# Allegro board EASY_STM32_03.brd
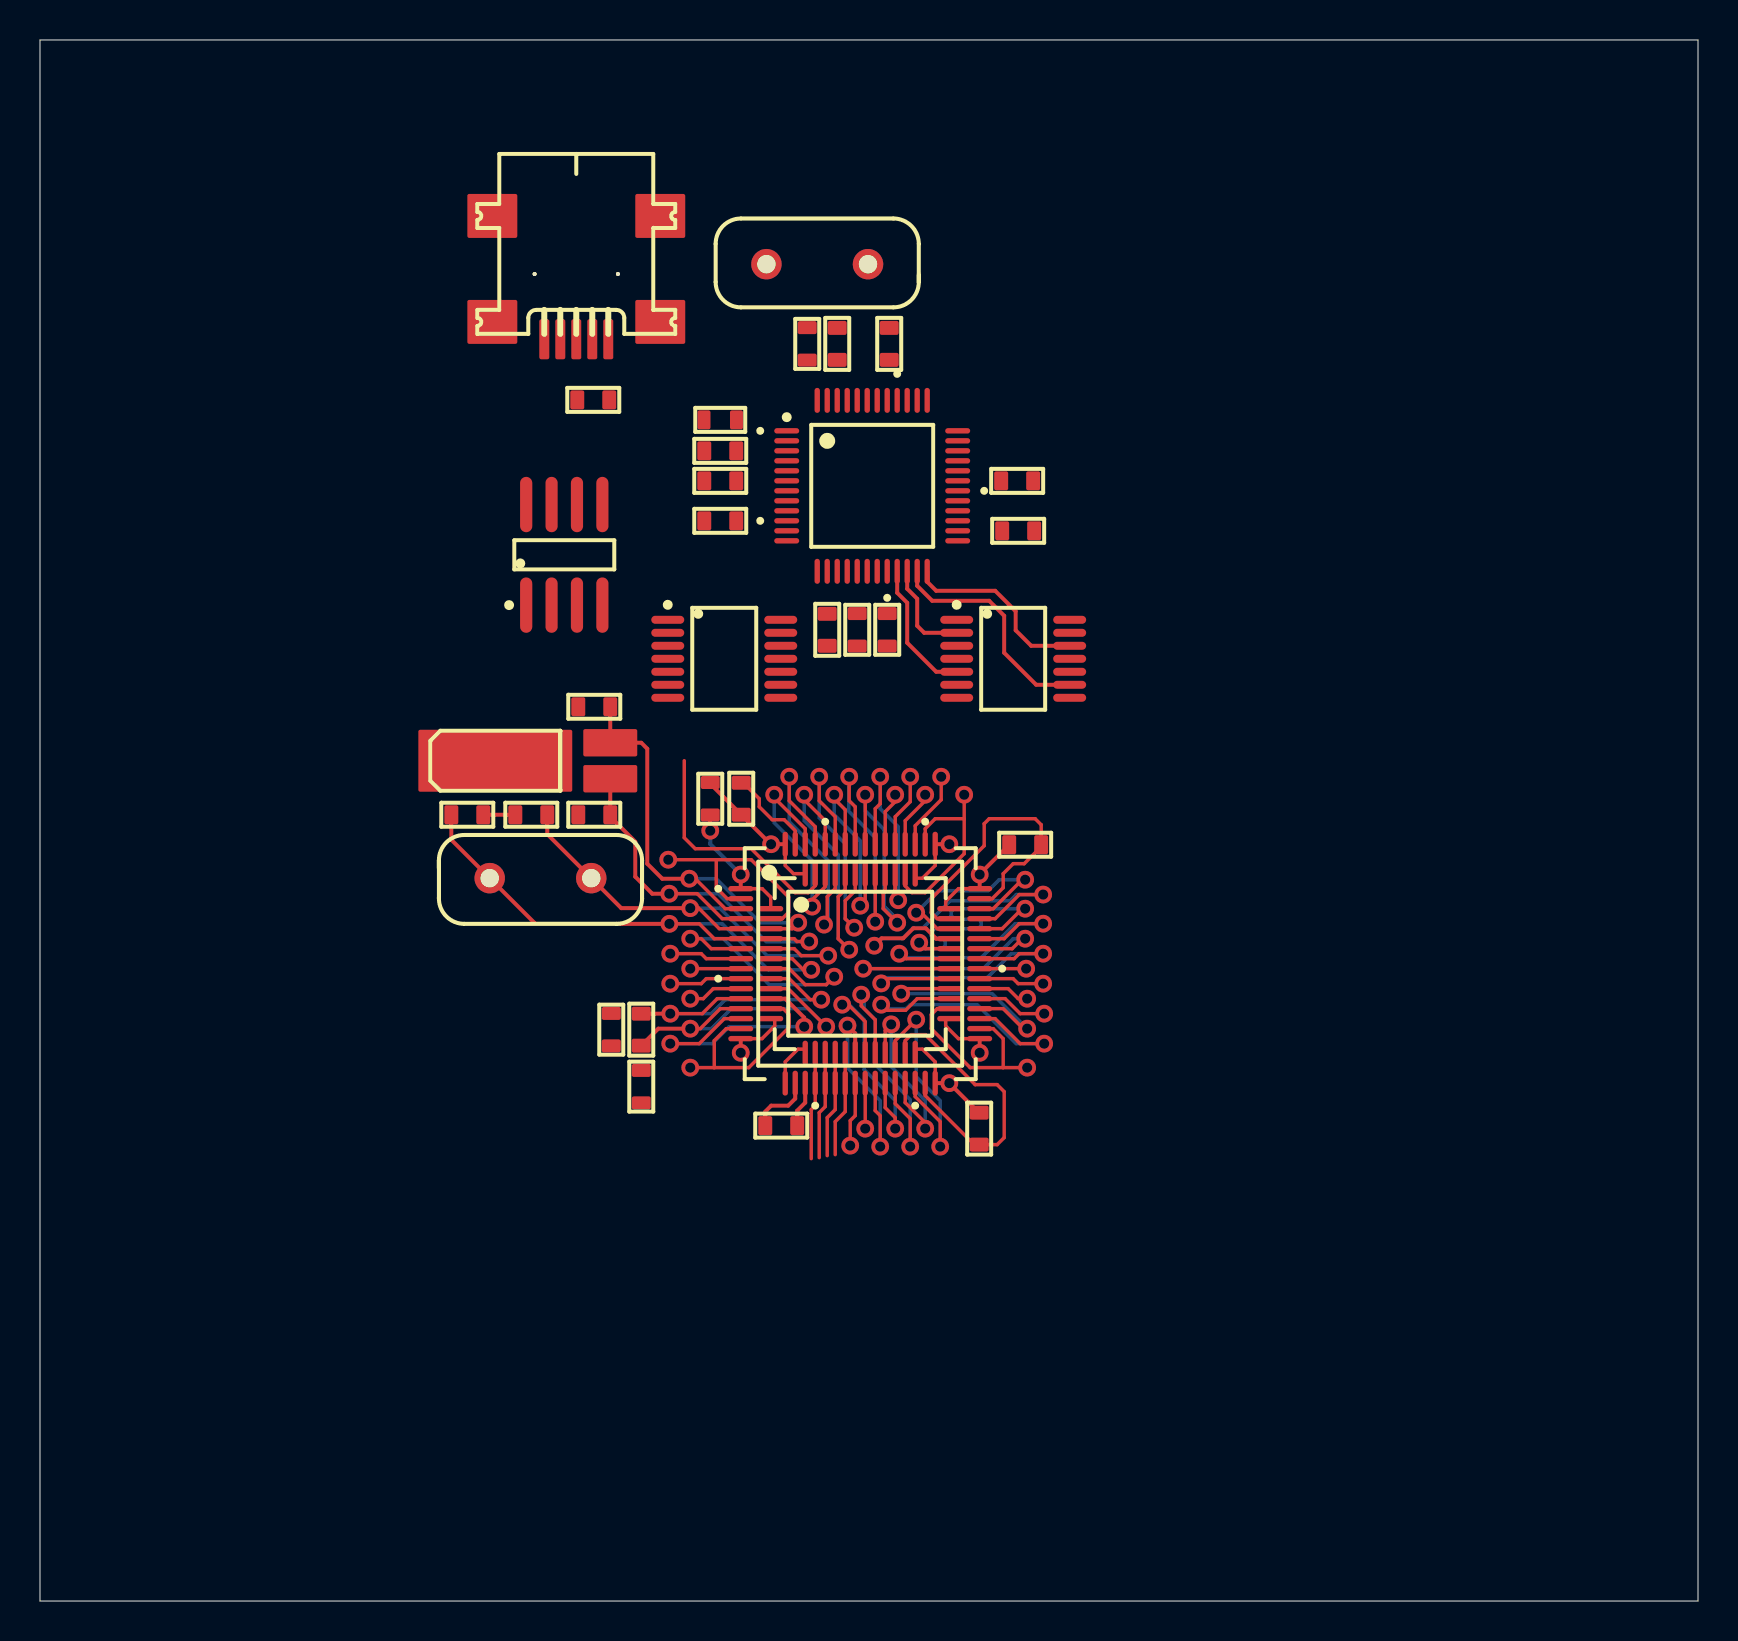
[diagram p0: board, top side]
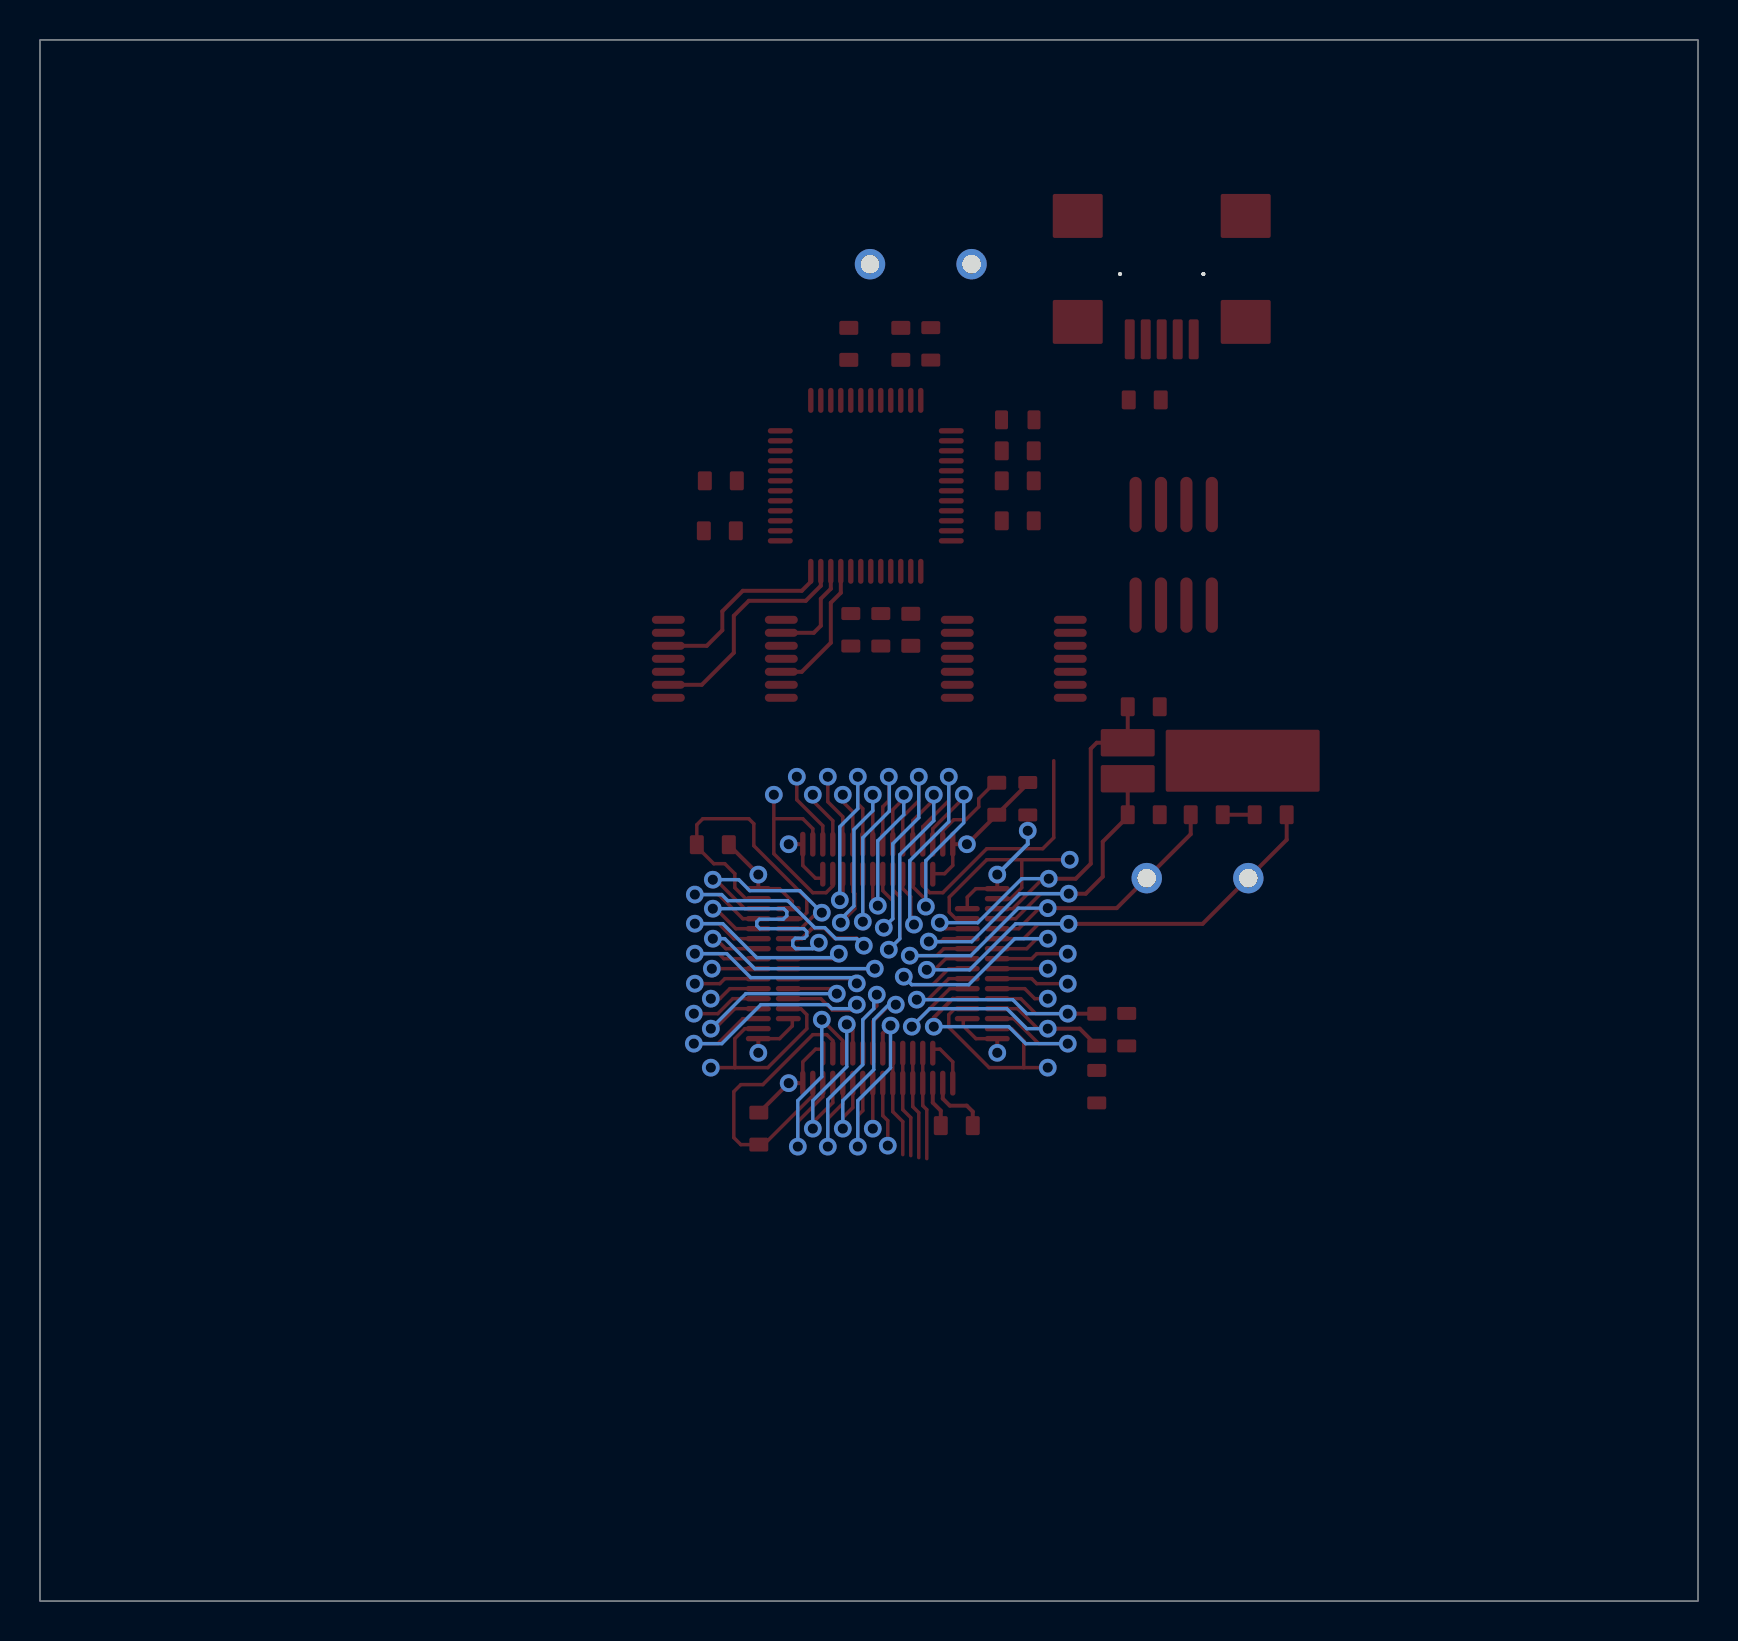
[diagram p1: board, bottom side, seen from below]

Outline 82.92 x 78.08 mm; copper layers: TOP, BOTTOM. Coordinates in mm from the lower left corner of the outline.
Outline path: 0,78.08 0,0 82.92,0 82.92,78.08 0,78.08

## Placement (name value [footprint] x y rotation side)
C1  22pF  [CAP0603_B]  24.57 39.33 180 top
C2  22p  [CAP0603_B]  21.37 39.33 0 top
C3  15p  [CAP0603_B]  27.72 39.33 180 top
C4  15p  [CAP0603_B]  27.72 44.73 180 top
C5  100n  [CAP0603_B]  30.07 28.58 90 top
C6  100n  [CAP0603_B]  46.97 23.63 270 top
C7  100n  [CAP0603_B]  49.27 37.83 0 top
C8  100n  [CAP0603_B]  35.07 40.13 90 top
C9  100n  [CAP0603_B]  37.07 23.78 180 top
C10  10u  [CAP0603_B]  27.67 60.08 0 top
C11  100n  [CAP0603_B]  34.02 57.53 180 top
C12  100n  [CAP0603_B]  42.47 62.88 90 top
C14  100n  [CAP0603_B]  34.02 54.03 180 top
C15  100n  [CAP0603_B]  39.37 48.58 270 top
C16  100n  [CAP0603_B]  48.92 53.53 0 top
C17  100n  [CAP0603_B]  48.87 56.03 0 top
C18  100n  [CAP0603_B]  39.87 62.88 90 top
C19  100n  [CAP0603_B]  34.02 56.03 180 top
J1  USB_MB  [HIROSE-US60-MB-5ST]  26.82 72.38 180 top
R1  0R  [RES0603_B]  33.52 40.13 90 top
R2  0R  [RES0603_B]  30.07 25.73 270 top
R3  0R  [RES0603_B]  28.57 28.58 270 top
R4  470R  [RES0603_B]  38.37 62.88 270 top
R7  10K  [RES0603_B]  42.37 48.58 270 top
R13  1K5  [RES0603_B]  34.02 59.08 0 top
R14  100K  [RES0603_B]  40.87 48.58 270 top
U1  STM32F103RCT6  [LQFP64_MODIFIED]  41.02 31.88 0 top
U2  STM32F100  [LQFP48L_MODIFIED]  41.02 31.88 0 top
U3  FT2232D  [LQFP48L]  41.62 55.78 0 top
U4  AT93C46-10SI-2.7  [SOIC8S1JEDECM]  26.22 52.33 0 top
U5  74LVC125A  [TSOP65P640X120-14]  48.67 47.13 270 top
U6  74LVC125A  [TSOP65P640X120-14]  34.22 47.13 270 top
Y1  8M  [XTAL_DIP]  22.49 36.16 0 top
Y2  32.768KHz  [RTC-CRYSTAL]  24.52 42.03 90 top
Y3  6M  [XTAL_DIP]  41.41 66.86 180 top

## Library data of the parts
C1-C9 = C1005_0: User Part Number: pn; Tolerance: RichardLC
C10-C12 C14-C19 = CAP NP_0: User Part Number: pn; Tolerance: RichardLC
J1 = CON9: User Part Number: pn; Tolerance: RichardLC
R1-R4 R7 R13 R14 = R_0: User Part Number: pn; Tolerance: RichardLC
U1 = STM32F103RCT6_2: User Part Number: pn; Tolerance: RichardLC
U2 = STM32F100_1: User Part Number: pn; Tolerance: RichardLC
U3 = FT2232D_0: User Part Number: pn; Tolerance: RichardLC
U4 = 93C46_2: User Part Number: pn; Tolerance: RichardLC
U5 U6 = 74HC125/LCC_0: User Part Number: pn; Tolerance: RichardLC
Y1 Y3 = ZTB: Tolerance: ***; User Part Number: ***
Y2 = ZTA_0: User Part Number: pn; Tolerance: RichardLC

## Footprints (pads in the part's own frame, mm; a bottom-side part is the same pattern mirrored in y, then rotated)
CAP0603_B
  custom 0.175x0.175 smd: 1(-0.8,0) 2(0.8,0)
HIROSE-US60-MB-5ST
  round 0.2 hole 0.9 unplated: (-2.083,6.005) (2.083,6.005)
  custom 0.125x0.125 smd: 1(-1.6,9.271) 2(-0.8,9.271) 3(0,9.271) 4(0.8,9.271) 5(1.6,9.271)
  custom 0.55x0.55 smd: 6(-4.2,3.1) 7(4.2,3.1) 8(-4.2,8.4) 9(4.2,8.4)
LQFP48L
  oval 1.25x0.27 smd: 1(-4.275,2.75) 2(-4.275,2.25) 3(-4.275,1.75) 4(-4.275,1.25) 5(-4.275,0.75) 6(-4.275,0.25) 7(-4.275,-0.25) 8(-4.275,-0.75) 9(-4.275,-1.25) 10(-4.275,-1.75) 11(-4.275,-2.25) 12(-4.275,-2.75) 25(4.275,-2.75) 26(4.275,-2.25) 27(4.275,-1.75) 28(4.275,-1.25) 29(4.275,-0.75) 30(4.275,-0.25) 31(4.275,0.25) 32(4.275,0.75) 33(4.275,1.25) 34(4.275,1.75) 35(4.275,2.25) 36(4.275,2.75)
  oval 0.27x1.25 smd: 13(-2.75,-4.275) 14(-2.25,-4.275) 15(-1.75,-4.275) 16(-1.25,-4.275) 17(-0.75,-4.275) 18(-0.25,-4.275) 19(0.25,-4.275) 20(0.75,-4.275) 21(1.25,-4.275) 22(1.75,-4.275) 23(2.25,-4.275) 24(2.75,-4.275) 37(2.75,4.275) 38(2.25,4.275) 39(1.75,4.275) 40(1.25,4.275) 41(0.75,4.275) 42(0.25,4.275) 43(-0.25,4.275) 44(-0.75,4.275) 45(-1.25,4.275) 46(-1.75,4.275) 47(-2.25,4.275) 48(-2.75,4.275)
LQFP48L_MODIFIED
  oval 1.25x0.27 smd: 1(-4.475,2.75) 2(-4.475,2.25) 3(-4.475,1.75) 4(-4.475,1.25) 5(-4.475,0.75) 6(-4.475,0.25) 7(-4.475,-0.25) 8(-4.475,-0.75) 9(-4.475,-1.25) 10(-4.475,-1.75) 11(-4.475,-2.25) 12(-4.475,-2.75) 25(4.475,-2.75) 26(4.475,-2.25) 27(4.475,-1.75) 28(4.475,-1.25) 29(4.475,-0.75) 30(4.475,-0.25) 31(4.475,0.25) 32(4.475,0.75) 33(4.475,1.25) 34(4.475,1.75) 35(4.475,2.25) 36(4.475,2.75)
  oval 0.27x1.25 smd: 13(-2.75,-4.475) 14(-2.25,-4.475) 15(-1.75,-4.475) 16(-1.25,-4.475) 17(-0.75,-4.475) 18(-0.25,-4.475) 19(0.25,-4.475) 20(0.75,-4.475) 21(1.25,-4.475) 22(1.75,-4.475) 23(2.25,-4.475) 24(2.75,-4.475) 37(2.75,4.475) 38(2.25,4.475) 39(1.75,4.475) 40(1.25,4.475) 41(0.75,4.475) 42(0.25,4.475) 43(-0.25,4.475) 44(-0.75,4.475) 45(-1.25,4.475) 46(-1.75,4.475) 47(-2.25,4.475) 48(-2.75,4.475)
LQFP64_MODIFIED
  oval 1.25x0.27 smd: 1(-5.975,3.75) 2(-5.975,3.25) 3(-5.975,2.75) 4(-5.975,2.25) 5(-5.975,1.75) 6(-5.975,1.25) 7(-5.975,0.75) 8(-5.975,0.25) 9(-5.975,-0.25) 10(-5.975,-0.75) 11(-5.975,-1.25) 12(-5.975,-1.75) 13(-5.975,-2.25) 14(-5.975,-2.75) 15(-5.975,-3.25) 16(-5.975,-3.75) 33(5.975,-3.75) 34(5.975,-3.25) 35(5.975,-2.75) 36(5.975,-2.25) 37(5.975,-1.75) 38(5.975,-1.25) 39(5.975,-0.75) 40(5.975,-0.25) 41(5.975,0.25) 42(5.975,0.75) 43(5.975,1.25) 44(5.975,1.75) 45(5.975,2.25) 46(5.975,2.75) 47(5.975,3.25) 48(5.975,3.75)
  oval 0.27x1.25 smd: 17(-3.75,-5.975) 18(-3.25,-5.975) 19(-2.75,-5.975) 20(-2.25,-5.975) 21(-1.75,-5.975) 22(-1.25,-5.975) 23(-0.75,-5.975) 24(-0.25,-5.975) 25(0.25,-5.975) 26(0.75,-5.975) 27(1.25,-5.975) 28(1.75,-5.975) 29(2.25,-5.975) 30(2.75,-5.975) 31(3.25,-5.975) 32(3.75,-5.975) 49(3.75,5.975) 50(3.25,5.975) 51(2.75,5.975) 52(2.25,5.975) 53(1.75,5.975) 54(1.25,5.975) 55(0.75,5.975) 56(0.25,5.975) 57(-0.25,5.975) 58(-0.75,5.975) 59(-1.25,5.975) 60(-1.75,5.975) 61(-2.25,5.975) 62(-2.75,5.975) 63(-3.25,5.975) 64(-3.75,5.975)
RES0603_B
  custom 0.163x0.163 smd: 1(-0.812,0) 2(0.812,0)
RTC-CRYSTAL
  custom 0.343x0.343 smd: 1(-0.9,-4) 2(0.9,-4)
  custom 0.775x0.775 smd: 3(0,1.75)
SOIC8S1JEDECM
  oval 0.61x2.77 smd: 1(-1.905,-2.515) 2(-0.635,-2.515) 3(0.635,-2.515) 4(1.905,-2.515) 5(1.905,2.515) 6(0.635,2.515) 7(-0.635,2.515) 8(-1.905,2.515)
TSOP65P640X120-14
  oval 0.4x1.65 smd: 1(-1.95,-2.825) 2(-1.3,-2.825) 3(-0.65,-2.825) 4(0,-2.825) 5(0.65,-2.825) 6(1.3,-2.825) 7(1.95,-2.825) 8(1.95,2.825) 9(1.3,2.825) 10(0.65,2.825) 11(0,2.825) 12(-0.65,2.825) 13(-1.3,2.825) 14(-1.95,2.825)
XTAL_DIP
  round 1.524 hole 0.914: 1(0,0) 2(5.08,0)

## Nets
+3V3: C6.1 C7.1 C8.1 C9.1 C14.1 C15.1 C16.1 C17.1 R1.2 R2.2 R14.1 U1.19(VDD_4) U1.32(VDD_1) U1.48(VDD_2) U1.64(VDD_3) U2.24(VDD_1) U2.36(VDD_2) U2.48(VDD_3) U3.10(SI/WUA) U3.14(VCCIOA) U3.17(ADBUS6) U3.26(SI/WUB) U3.31(VCCIOB) U5.14(VCC)
+5V: C10.1 C11.1 C12.1 R4.1 U3.3(VCC1) U3.42(VCC2) U4.8(VCC)
GND: C1.2 C2.2 C3.2 C4.2 C6.2 C7.2 C8.2 C9.2 C10.2 C11.2 C12.2 C14.2 C15.2 C16.2 C17.2 C18.2 C19.2 J1.5 J1.6 J1.7 J1.8 J1.9 R3.2 R7.2 R14.2 U1.18(VSS_4) U1.31(VSS_1) U1.47(VSS_2) U1.63(VSS_3) U2.23(VSS_1) U2.35(VSS_2) U2.47(VSS_3) U3.9(GND1) U3.18(GND2) U3.25(GND3) U3.34(GND4) U3.45(AGND) U3.47(TEST) U4.5(GND) U4.7(NC) U5.7(GND) U6.7(GND) Y2.3
VBAT: R1.1 U1.1(VBAT) U2.1(VBAT)
VCC: U6.14(VCC)
VDDA: C5.1 R2.1 U1.13(VDDA) U2.9(VDDA)
VSSA: C5.2 R3.1 U1.12(VSSA) U2.8(VSSA)
BOOT0: U1.60(BOOT0) U2.44(BOOT0)
CTS: U3.37(BDBUS3)
DCD: U3.33(BDBUS6)
DSR: U3.35(BDBUS5)
DTR: U3.36(BDBUS4)
EECK: U3.1(EESK) U4.2(CLK)
EECS: U3.48(EECS) U4.1(CS)
EEDA: U3.2(EEDATA) U4.3(DI)
JT_SRSTN: U3.16(ADBUS7)
NRST: U1.7(NRST) U2.7(NRST)
OSC32_IN: C4.1 U1.3(PC14/OSC32_IN) U2.3(PC14/OSC32_IN) Y2.2
OSC32_OUT: C3.1 U1.4(PC15/OSC32/OUT) U2.4(PC15/OSC32_OUT) Y2.1
OSC_IN: C1.1 U1.5(PD0/OSC_IN) U2.5(PD0/OSC_IN) Y1.2
OSC_OUT: C2.1 U1.6(PD1/OSC_OUT) U2.6(PD1/OSC_OUT) Y1.1
PA0: U1.14(PA0-WKUP) U2.10(PA0/WKUP)
PA1: U1.15(PA1) U2.11(PA1)
PA2: U1.16(PA2) U2.12(PA2)
PA3: U1.17(PA3) U2.13(PA3)
PA4: U1.20(PA4) U2.14(PA4)
PA5: U1.21(PA5) U2.15(PA5)
PA6: U1.22(PA6) U2.16(PA6)
PA7: U1.23(PA7) U2.17(PA7)
PA8: U1.41(PA8) U2.29(PA8)
PA9: U1.42(PA9) U2.30(PA9)
PA10: U1.43(PA10) U2.31(PA10)
PA11: U1.44(PA11) U2.32(PA11)
PA12: U1.45(PA12) U2.33(PA12)
PA13: U1.46(PA13) U2.34(PA13)
PA14: U1.49(PA14) U2.37(PA14)
PA15: U1.50(PA15) U2.38(PA15)
PB0: U1.26(PB0) U2.18(PB0)
PB1: U1.27(PB1) U2.19(PB1)
PB2: U1.28(PB2/BOOT1) U2.20(PB2)
PB3: U1.55(PB3) U2.39(PB3)
PB4: U1.56(PB4) U2.40(PB4)
PB5: U1.57(PB5) U2.41(PB5)
PB6: U1.58(PB6) U2.42(PB6)
PB7: U1.59(PB7) U2.43(PB7)
PB8: U1.61(PB8) U2.45(PB8)
PB9: U1.62(PB9) U2.46(PB9)
PB10: U1.29(PB10) U2.21(PB10)
PB11: U1.30(PB11) U2.22(PB11)
PB12: U1.33(PB12) U2.25(PB12)
PB13: U1.34(PB13) U2.26(PB13)
PB14: U1.35(PB14) U2.27(PB14)
PB15: U1.36(PB15) U2.28(PB15)
PC0: U1.8(PC0)
PC1: U1.9(PC1)
PC2: U1.10(PC2)
PC3: U1.11(PC3)
PC4: U1.24(PC4)
PC5: U1.25(PC5)
PC6: U1.37(PC6)
PC7: U1.38(PC7)
PC8: U1.39(PC8)
PC9: U1.40(PC9)
PC10: U1.51(PC10)
PC11: U1.52(PC11)
PC12: U1.53(PC12)
PC13: U1.2(PC13/TAMPER/RTC) U2.2(PC13/TAMPER/RTC)
PD2: U1.54(PD2)
RI: U3.32(BDBUS7)
RTS: U3.38(BDBUS2)
RXD: U3.39(BDBUS1)
SRST: U3.11(ACBUS3)
SRST_OE: U3.12(ACBUS2)
TRST: U3.13(ACBUS1)
TRST_OE: U3.15(ACBUS0)
TXD: U3.40(BDBUS0)
USB_CLK: U3.24(ADBUS0) U5.12(A4)
USB_TDI: U3.23(ADBUS1) U5.9(A3)
USB_TDO: U3.22(ADBUS2) U5.2(A1)
USB_TMS: U3.21(ADBUS3) U5.5(A2)
N50123: J1.3 R13.1 U3.7(USBDP)
N50127: C18.1 R4.2 U3.46(AVCC)
N50535: R7.1 U3.20(ADBUS4)
N50793: U3.43(XTIN) Y3.1
N50801: U3.44(XTOUT) Y3.2
N51025: J1.1
N51319: R13.2 U3.5(R\S\T\O\U\T\)
N51335: J1.2 U3.8(USBDM)
N51347: U3.4(R\E\S\E\T\)
N51363: C19.1 U3.6(3V3OUT)
N51511: U4.4(DO)

Pads without a net: J1 4; U3 19 27 28 29 30 41; U4 6; U5 1 3 4 6 8 10 11 13; U6 1 2 3 4 5 6 8 9 10 11 12 13

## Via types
v1: diameter 0.889, hole 0.508, TOP to BOTTOM, 84 vias

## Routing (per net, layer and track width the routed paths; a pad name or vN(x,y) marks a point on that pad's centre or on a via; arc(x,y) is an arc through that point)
+3V3: length 19.8
  TOP w0.175: U1.48 45.93,35.63 45.3,34.99 45.3,34.63 ; 43.77,27.6 44.13,27.6 44.77,26.97 U1.32 ; 38.27,36.38 37.68,36.38 37.27,36.79 U1.64
  TOP w0.2: U1.19 38.27,24.93 37.87,24.53 C9.1 ; U1.64 v1(36.56,37.85) 36.55,37.85 C8.1 33.52,40.88 R1.2 ; C7.1 47,36.35 v1(47,36.33) U1.48 ; 46.95,24.43 v1(45.48,25.9) U1.32
GND: length 51.8
  TOP w0.175: 43.27,27.6 43.27,28.03 43.57,28.33 44.27,28.33 46.77,25.83 47.87,25.83 48.22,25.48 48.22,23.18 47.87,22.83 C6.2 46.72,22.83 44.27,25.28 U1.31 ; C8.2 35.17,40.93 35.97,40.13 35.97,39.73 36.62,39.08 37.22,39.08 37.77,38.53 U1.63 ; U2.47 38.77,35.78 38.42,35.43 37.77,35.43 35.57,37.63 32.77,37.63 32.22,38.18 32.22,42.03 ; U1.47 47.62,35.13 48.17,35.68 48.17,36.38 48.67,36.88 49.22,36.88 50.07,37.73 C7.2 50.07,38.83 49.77,39.13 47.47,39.13 47.22,38.88 47.22,37.78 44.57,35.13 44.57,34.43 44.87,34.13 U2.35
  TOP w0.2: U1.18 37.77,25.13 37.42,24.78 36.57,24.78 36.27,24.48 C9.2 ; C2.2 C1.2
VBAT: length 6.6
  TOP w0.175: U1.1 36.12,35.63 36.55,35.2 U2.1
  TOP w0.2: R1.1 v1(33.52,38.53) ; U1.1 v1(35.05,36.33)
  BOTTOM w0.2: v1(33.52,38.53) 33.52,37.86 v1(35.05,36.33)
VDDA: length 16.9
  TOP w0.175: U1.13 34.02,29.63 33.02,28.63 v1(32.52,28.63) ; U2.9 37.42,30.63 v1(39.32,28.73)
  TOP w0.2: v1(32.52,28.63) 30.92,28.63 C5.1
  BOTTOM w0.175: v1(32.52,28.63) 33.57,28.63 34.57,29.63 38.42,29.63 v1(39.32,28.73)
VSSA: length 16.1
  TOP w0.175: v1(31.52,29.38) 33.12,29.38 33.87,30.13 U1.12 ; U2.8 37.47,31.13 38.52,30.08 v1(39.07,30.08)
  TOP w0.2: v1(31.52,29.38) C5.2
  BOTTOM w0.175: v1(31.52,29.38) 33.57,29.38 34.27,30.08 v1(39.07,30.08)
BOOT0: length 15.7
  TOP w0.175: U1.60 39.27,39.03 38.22,40.08 v1(38.22,40.33) ; v1(40.47,32.58) 39.92,33.13 39.92,35.23 40.27,35.58 U2.44
  BOTTOM w0.175: v1(38.22,40.33) 38.22,39.03 39.92,37.33 39.92,33.13 v1(40.47,32.58)
NRST: length 14.7
  TOP w0.175: v1(32.52,33.13) 33.07,33.13 33.57,32.63 U1.7 ; U2.7 37.47,31.63 38.27,30.83 39.32,30.83 v1(39.72,31.23)
  BOTTOM w0.175: v1(32.52,33.13) 34.17,33.13 36.47,30.83 39.32,30.83 v1(39.72,31.23)
OSC32_IN: length 23
  TOP w0.175: v1(32.47,36.13) 32.77,36.13 34.27,34.63 U1.3 ; U2.3 37.62,33.63 v1(37.92,33.93)
  TOP w0.2: v1(32.47,36.13) 31.12,36.13 30.37,36.88 30.37,42.63 30.07,42.93 Y2.2 C4.1
  BOTTOM w0.175: v1(37.92,33.93) 36.02,33.93 33.82,36.13 v1(32.47,36.13)
OSC32_OUT: length 21.5
  TOP w0.175: U1.4 34.12,34.13 32.87,35.38 v1(31.47,35.38) ; v1(38.47,32.98) 37.86,32.98 37.72,33.13 U2.4
  TOP w0.2: v1(31.47,35.38) 30.62,35.38 29.77,36.23 29.77,37.98 28.52,39.23 C3.1 Y2.1
  BOTTOM w0.175: v1(31.47,35.38) 33.92,35.38 36.32,32.98 38.46,32.98 v1(38.47,32.98)
OSC_IN: length 23.5
  TOP w0.175: U2.5 37.72,32.63 38.07,32.28 v1(39.42,32.28) ; v1(32.52,34.66) 32.94,34.66 33.97,33.63 U1.5
  TOP w0.2: C1.1 25.37,38.35 Y1.2 29.07,34.66 v1(32.52,34.66)
  BOTTOM w0.175: v1(39.42,32.28) 36.37,32.28 33.99,34.66 v1(32.52,34.66)
OSC_OUT: length 28.1
  TOP w0.175: v1(31.48,33.87) 32.98,33.87 33.72,33.13 U1.6 ; v1(38.57,31.57) 38.18,31.57 37.62,32.13 U2.6
  TOP w0.2: v1(31.48,33.87) 24.78,33.87 Y1.1 20.57,38.08 C2.1
  BOTTOM w0.175: v1(31.48,33.87) 34.13,33.87 36.43,31.57 v1(38.57,31.57)
PA0: length 13.6
  TOP w0.175: v1(31.52,27.88) 32.97,27.88 34.22,29.13 U1.14
  TOP w0.2: U2.10 37.27,30.13 38.22,29.18 v1(38.22,28.73)
  BOTTOM w0.175: v1(38.22,28.73) 34.47,28.73 33.62,27.88 v1(31.52,27.88)
PA1: length 10.2
  TOP w0.175: v1(32.52,26.68) 33.72,26.68 ; 33.72,26.68 35.45,26.68 37.47,28.7 37.47,29.33 37.17,29.63 36.75,29.63 ; 33.72,26.68 33.72,28.03 34.32,28.63 U1.15
PA2: length 3
  TOP w0.175: U1.16 36.11,28.13 36.75,28.76 36.75,29.13
  TOP w0.2: U1.16 v1(35.05,27.42)
PA3: length 2.3
  TOP w0.175: 38.27,27.6 37.91,27.6 37.27,26.97 U1.17
PA4: length 5.6
  TOP w0.175: 38.57,22.13 38.57,24.58 38.77,24.78 U1.20 U2.14 38.77,27.6
PA5: length 5.5
  TOP w0.175: 38.97,22.18 38.97,24.43 39.27,24.73 U1.21 U2.15 39.27,27.6
PA6: length 5.5
  TOP w0.175: 39.77,27.6 U2.16 U1.22 39.77,24.58 39.37,24.18 39.37,22.28
PA7: length 5.5
  TOP w0.175: 40.27,27.6 U2.17 U1.23 40.27,24.48 39.77,23.98 39.77,22.33
PA8: length 15.5
  TOP w0.175: U1.41 48.72,32.13 48.97,32.38 v1(50.17,32.38) ; v1(42.07,30.89) 42.09,30.89 42.32,31.13 U2.29
  BOTTOM w0.175: v1(42.07,30.89) 42.36,31.18 47.37,31.18 48.57,32.38 v1(50.17,32.38)
PA9: length 15.5
  TOP w0.175: U1.42 48.62,32.63 49.12,33.13 v1(49.27,33.13) ; v1(41.17,31.63) U2.30
  BOTTOM w0.175: v1(49.27,33.13) 48.67,33.13 47.17,31.63 v1(41.17,31.63)
PA10: length 14.1
  TOP w0.175: U1.43 48.22,33.13 48.97,33.88 v1(50.17,33.88) ; v1(42.97,32.38) 43.07,32.38 43.32,32.13 U2.31
  BOTTOM w0.175: v1(50.17,33.88) 48.77,33.88 47.07,32.18 43.17,32.18 v1(42.97,32.38)
PA11: length 15.5
  TOP w0.175: v1(43.97,32.93) 44.27,32.63 U2.32 ; U1.44 48.12,33.63 49.12,34.63 v1(49.27,34.63)
  BOTTOM w0.175: v1(43.97,32.93) 44.27,32.63 45.12,32.63 45.27,32.78 45.27,33.03 45.15,33.15 44.7,33.15 44.57,33.28 44.57,33.48 44.72,33.63 46.92,33.63 47.07,33.78 47.07,33.98 46.95,34.1 45.75,34.1 45.57,34.28 45.57,34.48 45.72,34.63 v1(49.27,34.63)
PA12: length 17.5
  TOP w0.175: U1.45 47.77,34.13 48.98,35.33 v1(50.17,35.33)
  TOP w0.2: v1(41.72,32.78) 42.09,33.15 43.17,33.15 43.67,33.65 44.3,33.65 44.82,33.13 U2.33
  BOTTOM w0.175: v1(41.72,32.78) 42.07,33.13 43.12,33.13 43.67,33.68 44.17,33.68 45.52,35.03 48.52,35.03 48.83,35.33 v1(50.17,35.33)
PA13: length 11
  TOP w0.175: U1.46 47.67,34.63 49.12,36.08 v1(49.27,36.08) ; U2.34 44.87,33.63 44.07,34.43 v1(43.82,34.43)
  BOTTOM w0.175: v1(43.82,34.43) 44.92,35.53 47.42,35.53 47.97,36.08 v1(49.27,36.08)
PA14: length 3
  TOP w0.175: 43.77,36.15 44.13,36.15 44.77,36.79 U1.49
  TOP w0.2: U1.49 v1(45.48,37.85)
PA15: length 10.4
  TOP w0.175: U2.38 43.27,35.77 43.61,35.43 44.27,35.43 46.22,37.38 46.22,39.13 ; 46.22,39.13 v1(46.22,40.33) ; 46.22,39.13 44.77,39.13 44.27,38.63 U1.50
PB0: length 11.5
  TOP w0.175: U1.26 41.77,24.53 42.02,24.28 v1(42.02,22.73)
  TOP w0.2: U2.18 40.77,28.39 v1(40.38,28.78)
  BOTTOM w0.175: v1(42.02,22.73) 42.02,25.03 40.38,26.66 v1(40.38,28.78)
PB1: length 13.1
  TOP w0.175: v1(42.77,23.63) 42.77,24.18 42.27,24.68 U1.27 ; U2.19 41.27,28.98 40.42,29.83 v1(40.12,29.83)
  BOTTOM w0.175: v1(40.12,29.83) 40.47,29.83 41.22,29.08 41.22,26.58 42.77,25.03 v1(42.77,23.63)
PB2: length 15.3
  TOP w0.175: v1(43.52,22.73) 43.52,24.13 42.77,24.88 U1.28 ; v1(41.07,30.33) 41.07,29.77 41.77,29.07 U2.20
  BOTTOM w0.175: v1(43.52,22.73) 43.52,25.08 41.77,26.83 41.77,29.08 41.22,29.63 41.22,30.18 v1(41.07,30.33)
PB3: length 11.4
  TOP w0.175: U1.55 41.77,39.63 42.02,39.88 v1(42.02,41.23)
  TOP w0.2: U2.39 42.77,35.2 v1(42.92,35.05)
  BOTTOM w0.175: v1(42.92,35.05) 42.92,38.73 42.02,39.63 v1(42.02,41.23)
PB4: length 12.3
  TOP w0.175: U1.56 v1(41.27,40.33) ; v1(42.87,33.93) 42.17,34.63 42.17,35.38 42.27,35.48 U2.40
  BOTTOM w0.175: v1(41.27,40.33) 41.27,39.53 42.21,38.58 42.21,34.76 42.87,34.1 v1(42.87,33.93)
PB5: length 13.7
  TOP w0.175: v1(40.47,41.23) 40.47,40.03 40.77,39.73 U1.57 ; U2.41 v1(41.77,33.98)
  BOTTOM w0.175: v1(41.77,33.98) 41.77,38.18 40.45,39.5 40.45,41.2 v1(40.47,41.23)
PB6: length 10.5
  TOP w0.175: U1.58 40.27,39.58 39.72,40.13 v1(39.72,40.33) ; U2.42 41.27,35.03 v1(41.02,34.78)
  BOTTOM w0.175: v1(39.72,40.33) 39.72,39.33 41.02,38.03 v1(41.02,34.78)
PB7: length 15
  TOP w0.175: U1.59 39.77,39.23 38.97,40.03 v1(38.97,41.23) ; v1(40.72,33.68) 40.27,34.13 40.27,35.03 40.77,35.53 U2.43
  BOTTOM w0.175: v1(40.72,33.68) 40.27,34.13 40.27,37.88 38.97,39.18 v1(38.97,41.23)
PB8: length 15
  TOP w0.175: v1(37.47,41.23) 37.47,40.03 38.77,38.73 U1.61 ; U2.45 39.77,35.63 39.37,35.23 39.37,33.99 v1(39.21,33.83)
  BOTTOM w0.175: v1(39.21,33.83) 39.42,34.04 39.42,37.03 37.47,38.98 v1(37.47,41.23)
PB9: length 11.4
  TOP w0.175: v1(38.62,34.73) 38.62,35.07 39.27,35.73 U2.46 ; v1(36.72,40.33) 36.72,40.18 38.27,38.63 U1.62
  BOTTOM w0.175: v1(38.62,34.73) 38.62,37.03 36.72,38.93 v1(36.72,40.33)
PB10: length 10.2
  TOP w0.175: U2.21 42.27,28.54 v1(42.57,28.84) ; v1(44.27,23.63) 44.27,23.93 43.27,24.93 U1.29
  BOTTOM w0.175: v1(44.27,23.63) 44.27,25.03 42.57,26.73 v1(42.57,28.84)
PB11: length 12.6
  TOP w0.175: v1(43.82,29.08) 42.77,28.03 U2.22 ; v1(45.02,22.73) 45.02,23.98 43.77,25.23 U1.30
  BOTTOM w0.175: v1(45.02,22.73) 45.02,25.03 43.82,26.23 v1(43.82,29.08)
PB12: length 3
  TOP w0.175: U1.33 45.93,28.13 45.3,28.76 45.3,29.13
  TOP w0.2: U1.33 v1(47,27.42)
PB13: length 10
  TOP w0.175: 48.17,26.68 46.52,26.68 44.57,28.63 44.57,29.33 44.87,29.63 45.3,29.63 ; 48.17,26.68 v1(49.37,26.68) ; 48.17,26.68 48.17,28.13 47.67,28.63 U1.34
PB14: length 16.6
  TOP w0.175: U2.27 43.87,30.13 43.29,29.55 42.35,29.55 v1(42.07,29.83) ; U1.35 47.77,29.13 49.02,27.88 v1(50.22,27.88)
  BOTTOM w0.175: v1(50.22,27.88) 48.82,27.88 46.87,29.83 43.52,29.83 43.32,29.63 42.27,29.63 v1(42.07,29.83)
PB15: length 12.3
  TOP w0.175: v1(49.37,28.63) 49.17,28.63 48.17,29.63 U1.36 ; U2.28 43.32,30.63 v1(43.07,30.38)
  BOTTOM w0.175: v1(49.37,28.63) 47.62,30.38 v1(43.07,30.38)
PC0: length 3.6
  TOP w0.175: v1(31.52,32.38) 33.07,32.38 33.32,32.13 U1.8
PC1: length 2.5
  TOP w0.175: U1.9 v1(32.52,31.63)
PC2: length 3.6
  TOP w0.175: v1(31.52,30.88) 33.07,30.88 33.32,31.13 U1.10
PC3: length 2.7
  TOP w0.175: U1.11 33.67,30.63 33.17,30.13 v1(32.52,30.13)
PC4: length 3.2
  TOP w0.175: v1(40.52,22.78) 40.52,24.03 40.77,24.28 U1.24
PC5: length 2.3
  TOP w0.175: U1.25 v1(41.27,23.63)
PC6: length 3.5
  TOP w0.175: U1.37 48.27,30.13 49.02,29.38 v1(50.22,29.38)
PC7: length 2.6
  TOP w0.175: U1.38 48.42,30.63 48.92,30.13 v1(49.37,30.13)
PC8: length 3.3
  TOP w0.175: U1.39 48.67,31.13 48.92,30.88 v1(50.17,30.88)
PC9: length 2.3
  TOP w0.175: U1.40 v1(49.32,31.63)
PC10: length 3.9
  TOP w0.175: v1(45.07,41.23) 45.07,40.08 43.77,38.78 U1.51
PC11: length 2.9
  TOP w0.175: v1(44.27,40.33) 44.27,40.03 43.27,39.03 U1.52
PC12: length 3.7
  TOP w0.175: v1(43.52,41.23) 43.52,39.98 42.77,39.23 U1.53
PC13: length 11.4
  TOP w0.175: 33.82,37.08 v1(31.42,37.08) ; 33.82,37.08 33.82,35.68 34.37,35.13 U1.2 ; 33.82,37.08 35.57,37.08 37.45,35.2 37.45,34.45 37.12,34.13 U2.2
PD2: length 2.7
  TOP w0.175: v1(42.77,40.33) 42.77,39.98 42.27,39.48 U1.54
USB_CLK: length 9.5
  TOP w0.2: U5.12 49.57,47.78 48.8,48.55 48.8,49.5 47.77,50.53 44.82,50.53 44.37,50.98 U3.24
USB_TDI: length 11.5
  TOP w0.2: U5.9 49.82,45.83 48.22,47.43 48.22,49.28 47.47,50.03 44.62,50.03 43.87,50.78 U3.23
USB_TDO: length 5.1
  TOP w0.2: U5.2 44.22,48.43 43.87,48.78 43.87,50.13 43.37,50.63 U3.22
USB_TMS: length 6.9
  TOP w0.2: U3.21 42.87,50.43 43.37,49.93 43.37,47.93 44.82,46.48 U5.5

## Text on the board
BODY_CENTER: FIGURE | SIZE | 0.508 | 0.8 | 0.8999 | 0.9144 | 1.0 | 2.4 | DRILL CHART: TOP to BOTTOM | ALL UNITS ARE IN MILLIMETERS | PLATED | QTY | 121 | 14 | 200 | 2 | 4
